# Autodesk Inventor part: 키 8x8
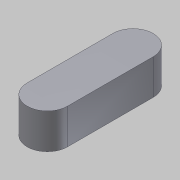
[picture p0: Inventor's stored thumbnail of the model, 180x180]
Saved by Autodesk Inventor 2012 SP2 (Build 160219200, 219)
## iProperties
Company: 한국ATC센터
Created: 2014-11
Part Number: 키 8x8
Document SubType Name: Modeling
Designer: KYOUNG IL JANG
Density: 7.86 g/cm^3
Material: 강, 연강
Mass: 10.2483 g
Surface Area: 7.8646 cm^2
Volume: 1.30386 cm^3
Author: KYOUNG IL JANG
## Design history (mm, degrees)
sketch "스케치1"
  geometry: L1 (28.264, -14)-(28.264, -31) reference; L2 (20.264, -31)-(20.264, -14) reference; A1 r 4 centre (24.264, -31) between (20.264, -31) and (28.264, -31) reference; A2 r 4 centre (24.264, -14) between (28.264, -14) and (20.264, -14) reference; 1 further point
extrude "돌출1" new body sketch "스케치1" distance "d0" = 7; taper "d1" = 0 deg
node "솔리드1"
node "참조1"
